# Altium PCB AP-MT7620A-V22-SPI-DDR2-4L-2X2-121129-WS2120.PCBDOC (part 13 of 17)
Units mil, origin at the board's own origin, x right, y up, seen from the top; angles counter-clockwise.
Board outline 7316 x 4279 mil, 4 copper layers (Top, Inner Layer 2, Inner Layer 3, Bottom), stack 35.4 mil thick; 640 components, 473 nets, 2041 pads, 2358 vias.
Unrouted connection lines stored in the file: 11.
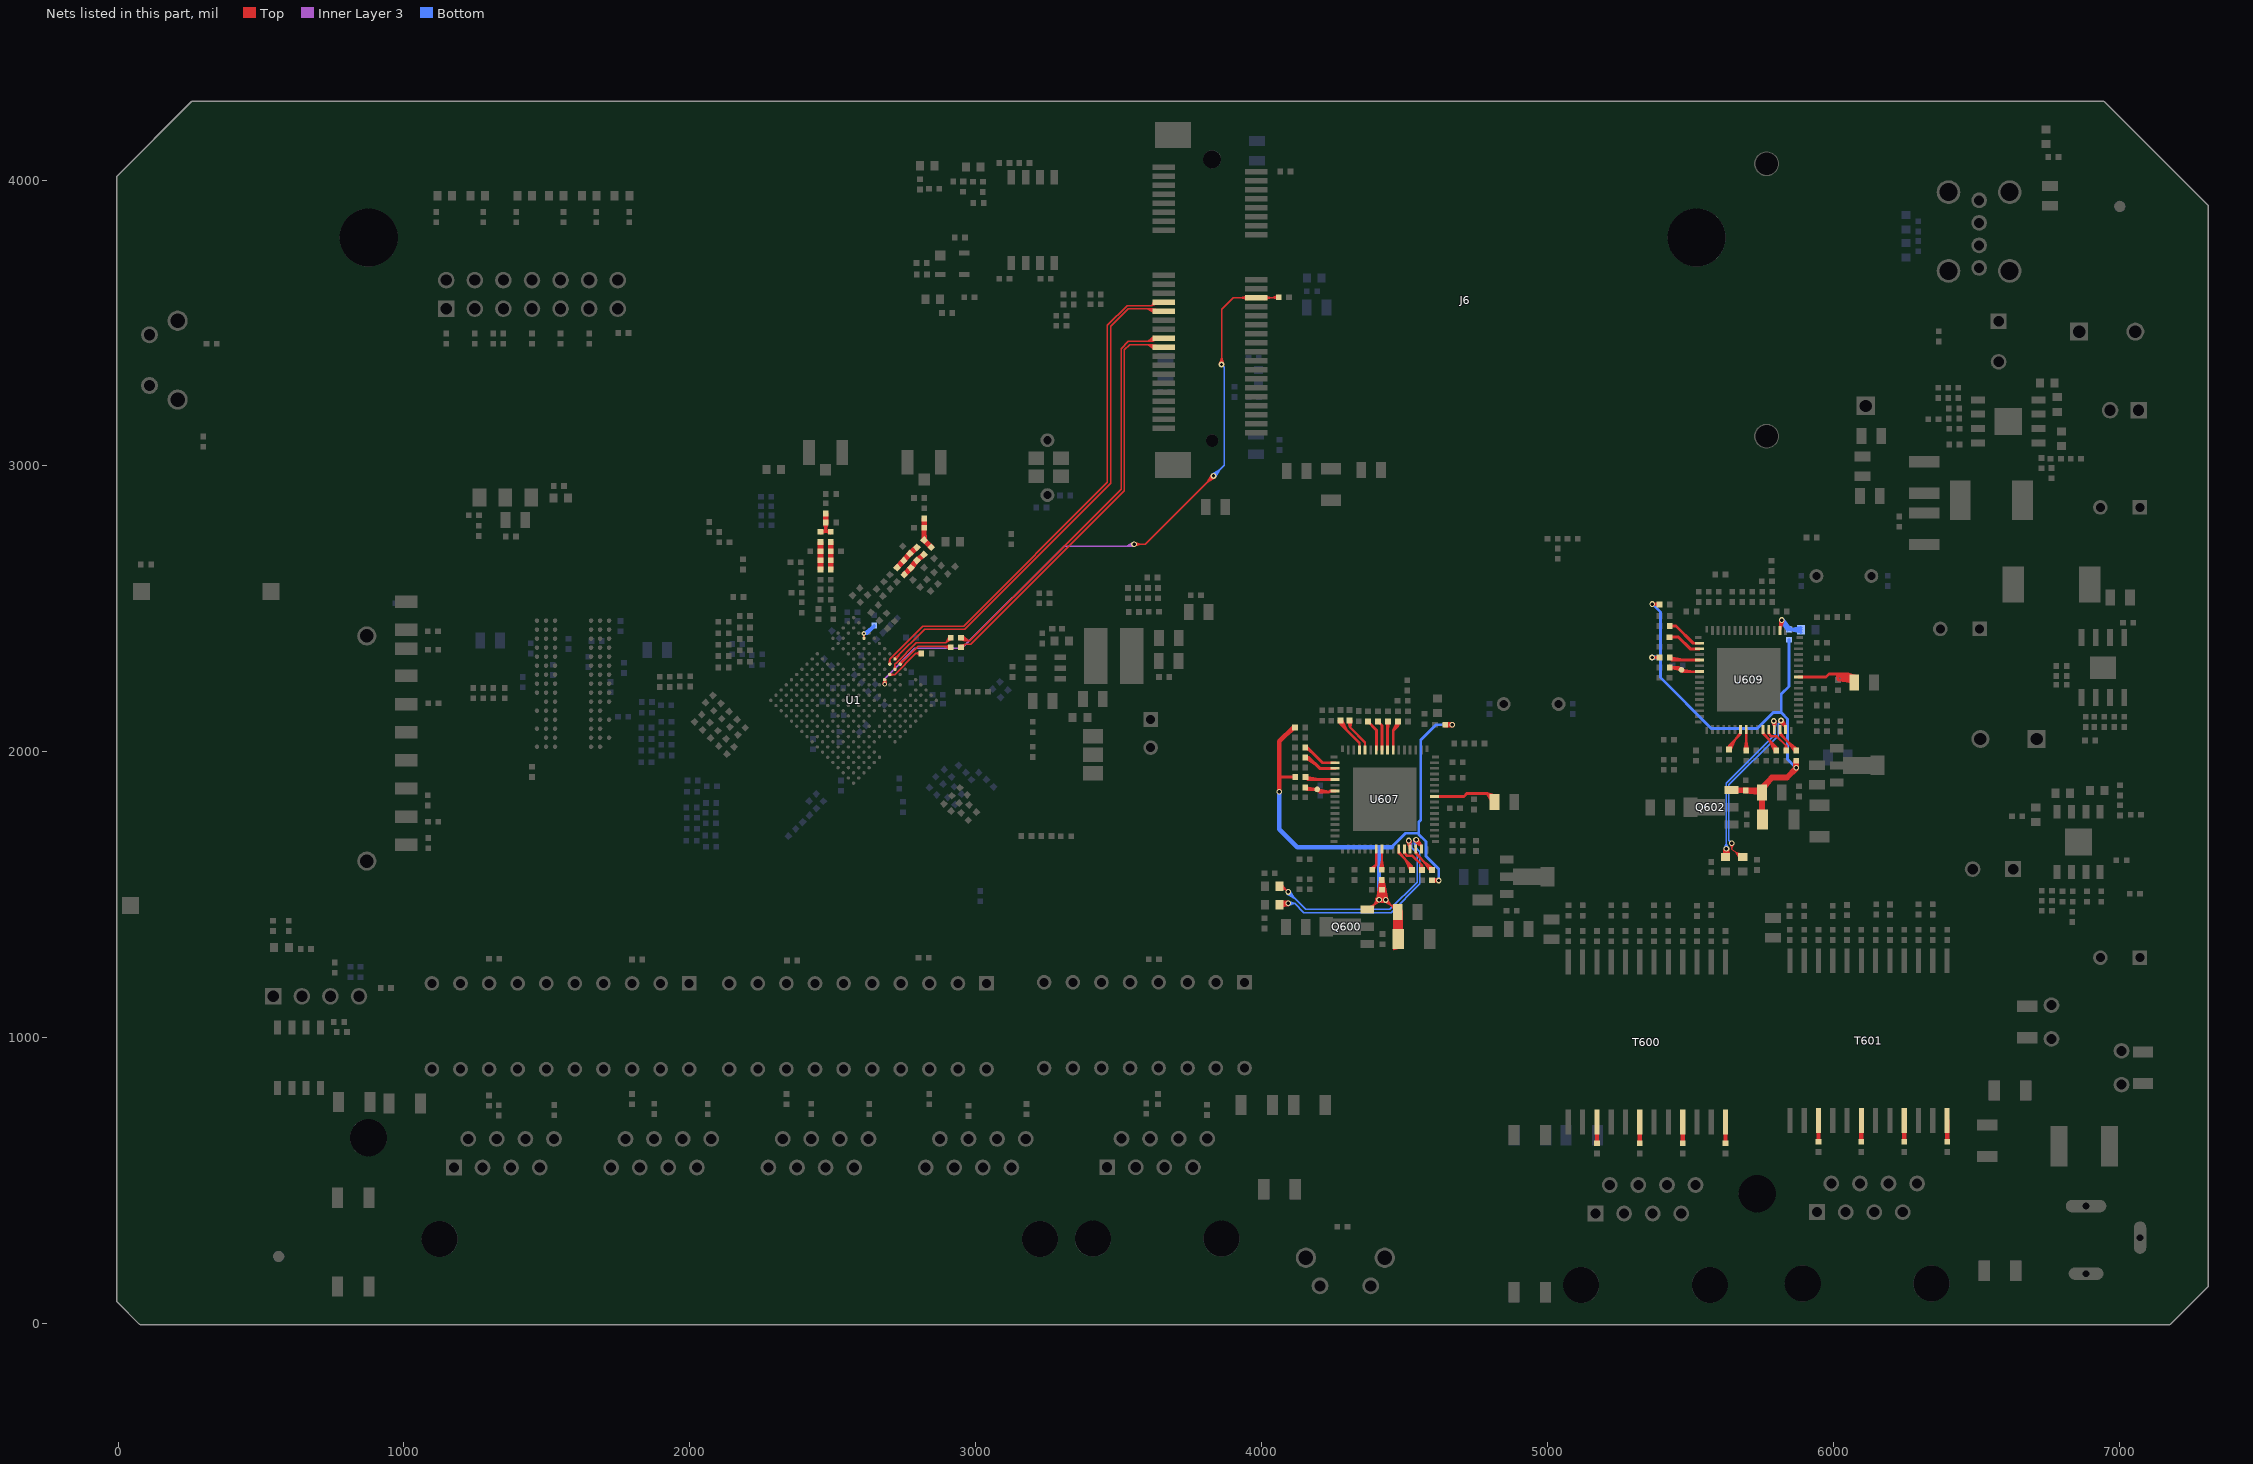
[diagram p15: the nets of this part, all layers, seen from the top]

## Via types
v1: diameter 20, hole 12, Top to Bottom, 2117 vias
v2: diameter 16, hole 8, Top to Bottom, 241 vias

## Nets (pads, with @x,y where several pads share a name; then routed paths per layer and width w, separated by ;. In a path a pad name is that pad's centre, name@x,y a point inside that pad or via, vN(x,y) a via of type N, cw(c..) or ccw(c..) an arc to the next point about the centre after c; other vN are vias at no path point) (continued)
P_LED0_IP1001: D15.1 U607.13 | length 1478.1
  Top w4.5: D15.1@4062.03,1520.92 4083,1520 ; D15.1@4062.33,1516.32 4083,1520 ; D15.1@4062.71,1525.39 4083,1520 ; D15.1@4063.59,1528 4083,1520 ; D15.1@4063.59,1530 4063.59,1520 4083,1520 ; D15.1@4064.8,1530.47 4083,1520 ; D15.1@4067.47,1534.13 4083,1520 ; D15.1@4070.93,1537.18 4083,1520 ; v1(4093,1510) 4083,1520 ; v1@4507.69,1687.78 U607.13@4517.22,1663.98 ; v1@4507.85,1687.19 U607.13@4516.91,1671.5 ; v1@4508.26,1686.17 U607.13@4519.57,1671.65 ; v1@4508.8,1685.23 U607.13@4522.19,1672.19 ; v1@4512.02,1689.08 U607.13@4517.22,1663.98 ; v1@4512.04,1688.95 U607.13@4516.91,1671.5 ; v1@4512.16,1688.5 U607.13@4519.57,1671.65 ; v1@4512.34,1688.07 U607.13@4522.19,1672.19 ; v1@4518.35,1690.48 U607.13@4522.19,1672.19 ; v1@4518.46,1690.02 U607.13@4519.57,1671.65 ; v1@4518.49,1689.54 U607.13@4516.91,1671.5 ; v1@4518.49,1689.58 U607.13@4517.22,1663.98 ; U607.13@4519.57,1660.82 4517.22,1660.82 v1@4517.22,1689.54 ; v1@4522.88,1690.86 U607.13@4522.19,1672.19 ; v1@4522.93,1688.58 U607.13@4516.91,1671.5 ; v1@4522.97,1688.96 U607.13@4517.22,1663.98 ; v1@4522.99,1689.73 U607.13@4519.57,1671.65 ; v1(4515.24,1689.54) v1@4517.22,1689.54 ; v1(4515.24,1689.54) U607.13@4517.22,1663.98 ; v1(4515.24,1689.54) U607.13@4516.91,1671.5 ; v1(4515.24,1689.54) U607.13@4522.19,1672.19 ; v1(4515.24,1689.54) U607.13@4519.57,1671.65 ; U607.13@4516.91,1671.5 v1@4517.22,1689.54 ; v1@4517.22,1689.54 U607.13@4522.19,1672.19 ; v1@4517.22,1689.54 U607.13@4519.57,1671.65
  Bottom w4.5: v1@4088.26,1503.87 4114.55,1488.45 ; v1@4090.83,1507.58 4114.55,1488.45 ; v1(4093,1510) 4154,1449 4449,1449 4544,1544 4544,1646 4525.5,1664.5 4525.5,1680.42 4516.38,1689.54 v1(4515.24,1689.54) v1@4515.7,1690 ; v1@4095.42,1512.17 4114.55,1488.45 ; v1@4099.13,1514.74 4114.55,1488.45
P_LED0_IP1001-2: D40.1 U609.13 | length 2448.2
  Top w4.5: D40.1@5613.62,1635.5 v1@5626,1660.21 ; D40.1@5617.85,1633.8 v1@5626,1660.21 ; v1@5618.25,1660.84 D40.1@5622.64,1635.62 ; v1@5618.3,1660.09 D40.1@5625.11,1635.51 ; v1@5618.35,1659.75 D40.1@5626,1637 ; v1@5618.33,1662.09 D40.1@5618.55,1636.06 ; v1@5618.43,1659.36 D40.1@5627.57,1635.53 ; v1@5618.61,1663.34 D40.1@5614.29,1636.85 ; v1@5618.78,1658.19 D40.1@5631.63,1635.82 ; v1@5619.31,1657.1 D40.1@5635.82,1636.46 ; D40.1@5622.26,1632.83 v1@5626,1660.21 ; v1@5622.76,1660.78 D40.1@5626,1637 ; v1@5622.75,1660.91 D40.1@5625.11,1635.51 ; v1@5622.76,1661.22 D40.1@5622.64,1635.62 ; v1@5622.78,1660.59 D40.1@5627.57,1635.53 ; v1@5622.83,1661.73 D40.1@5618.55,1636.06 ; v1@5622.88,1660.09 D40.1@5631.63,1635.82 ; D40.1@5623,1632.59 5627.41,1637 D40.1@5626,1637 ; v1@5622.99,1662.24 D40.1@5614.29,1636.85 ; v1@5623.06,1659.61 D40.1@5635.82,1636.46 ; D40.1@5625,1632.59 v1@5626,1660.21 ; D40.1@5627.75,1632.63 v1@5626,1660.21 ; v1@5628.83,1659.41 D40.1@5614.29,1636.85 ; v1@5629.05,1659.88 D40.1@5618.55,1636.06 ; v1@5629.09,1662.02 D40.1@5635.82,1636.46 ; v1@5629.19,1660.37 D40.1@5622.64,1635.62 ; v1@5629.21,1661.51 D40.1@5631.63,1635.82 ; v1@5629.23,1660.68 D40.1@5625.11,1635.51 ; v1@5629.24,1660.78 D40.1@5626,1637 ; v1@5629.25,1660.99 D40.1@5627.57,1635.53 ; D40.1@5632.22,1633.28 v1@5626,1660.21 ; v1@5632.41,1656.65 D40.1@5614.29,1636.85 ; v1@5633.01,1657.7 D40.1@5618.55,1636.06 ; v1@5633.44,1658.83 D40.1@5622.64,1635.62 ; v1@5633.54,1662.79 D40.1@5635.82,1636.46 ; v1@5633.61,1659.55 D40.1@5625.11,1635.51 ; v1@5633.65,1659.75 D40.1@5626,1637 ; v1@5633.72,1660.3 D40.1@5627.57,1635.53 ; v1@5633.73,1661.54 D40.1@5631.63,1635.82 ; D40.1@5636.56,1634.67 v1@5626,1660.21 ; v1@5784.34,2106.81 U609.13@5790.91,2089.84 ; v1@5784.43,2106.36 U609.13@5793.57,2082.46 ; v1@5784.59,2105.73 U609.13@5793.57,2089.65 ; v1@5784.98,2104.71 U609.13@5796.24,2089.84 ; v1@5788.75,2107.9 U609.13@5790.91,2089.84 ; v1@5788.8,2107.44 U609.13@5793.57,2089.65 ; v1@5788.78,2107.59 U609.13@5793.57,2082.46 ; v1@5788.91,2106.99 U609.13@5796.24,2089.84 ; U609.13@5793.57,2078.82 v1@5793.57,2108 ; v1@5795.21,2107.52 U609.13@5790.91,2089.84 ; v1@5795.22,2108.46 U609.13@5796.24,2089.84 ; v1@5799.46,2105.9 U609.13@5790.91,2089.84 ; v1@5799.69,2107.02 U609.13@5793.57,2089.65 ; v1@5799.72,2107.3 U609.13@5793.57,2082.46 ; v1@5799.75,2108.15 U609.13@5796.24,2089.84 ; D40.1@5614.29,1636.85 v1(5626,1661) ; D40.1@5618.55,1636.06 v1(5626,1661) ; D40.1@5622.64,1635.62 v1(5626,1661) ; D40.1@5625.11,1635.51 v1(5626,1661) ; D40.1@5626,1637 v1(5626,1661) ; v1(5626,1661) D40.1@5635.82,1636.46 ; v1(5626,1661) D40.1@5631.63,1635.82 ; v1(5626,1661) D40.1@5627.57,1635.53 ; U609.13@5790.91,2089.84 v1@5793.57,2108 ; U609.13@5790.91,2089.84 v1(5792,2108) ; v1(5792,2108) v1@5793.57,2108 ; v1(5792,2108) U609.13@5793.57,2082.46 ; v1(5792,2108) U609.13@5796.24,2089.84 ; v1(5792,2108) U609.13@5793.57,2089.65 ; U609.13@5793.57,2082.46 5795.25,2107.99 U609.13@5793.57,2089.65 ; U609.13@5793.57,2089.65 v1@5793.57,2108 ; v1@5793.57,2108 U609.13@5796.24,2089.84
  Bottom w4.5: v1@5618.42,1662.63 5626,1679.41 ; v1@5622.76,1661.29 5626,1679.41 ; v1(5626,1661) 5626,1679.41 ; v1@5629.24,1661.29 5626,1679.41 ; v1@5633.58,1662.63 5626,1679.41 ; v1@5784.67,2105.48 5797,2081.58 ; v1@5788.85,2107.2 5797,2081.58 ; v1@5795.22,2108.41 5797,2081.58 ; v1@5799.74,2108.33 5797,2081.58 ; 5626,1679.41 5625.5,1679.91 5625.5,1890.5 5797,2062 5797,2103 v1(5792,2108) 5797,2081.58
P_LED1_IP1001-2_1-CPU-RT0: R740.2 U609.14 | length 266
  Top w8: U609.14@5813.26,2078.82 5813.26,2062.05 ; 5838.34,2036.96 U609.14@5813.26,2067.99 ; R740.2@5865.41,2001.18 5843.18,2032.13 ; R740.2@5873.91,2009.59 5843.18,2032.13 ; 5813.26,2062.05 5868.99,2006.32 5868.99,2004.05 5869.99,2004.05 R740.2@5869.99,2005.05 5843.18,2032.13 ; 5813.26,2062.05 U609.14@5813.26,2067.99 ; 5813.26,2062.05 U609.14@5813.26,2067.99
P_LED1_IP1001_1-CPU-RT0: R714.2 U607.14 | length 266
  Top w8: U607.14@4539.26,1660.82 4539.26,1644.05 ; 4564.34,1618.96 U607.14@4539.26,1649.99 ; R714.2@4591.41,1583.18 4569.18,1614.13 ; R714.2@4599.91,1591.59 4569.18,1614.13 ; 4539.26,1644.05 4594.99,1588.32 4594.99,1586.05 4595.99,1586.05 R714.2@4595.99,1587.05 4569.18,1614.13 ; 4539.26,1644.05 U607.14@4539.26,1649.99 ; 4539.26,1644.05 U607.14@4539.26,1649.99
P_LED2_IP1001: D16.1 U607.15 | length 2809.2
  Top w4.5: D16.1@4063.43,1469.75 v1@4091.46,1470 ; D16.1@4063.59,1465 D16.1@4068.59,1470 ; D16.1@4063.59,1467 v1@4091.46,1470 ; D16.1@4063.75,1474.25 v1@4091.46,1470 ; D16.1@4064.02,1464.28 v1@4091.46,1470 ; D16.1@4064.81,1478.69 v1@4091.46,1470 ; D16.1@4065.29,1459.95 v1@4091.46,1470 ; D16.1@4067.27,1455.84 v1@4091.46,1470 ; v1@4088.35,1476.2 D16.1@4069.13,1456.93 ; v1@4089.33,1476.82 D16.1@4068.28,1461.1 ; v1@4089.66,1463.01 D16.1@4068.08,1477.62 ; v1@4090.38,1477.3 D16.1@4067.75,1465.06 ; v1@4090.75,1462.58 D16.1@4067.63,1473.65 ; v1@4091.06,1477.5 D16.1@4067.57,1467.43 ; v1@4091.27,1472.75 D16.1@4069.13,1456.93 ; v1@4091.71,1472.98 D16.1@4068.28,1461.1 ; v1@4091.77,1462.35 D16.1@4068.59,1470 ; v1@4091.86,1466.96 D16.1@4068.08,1477.62 ; v1@4091.89,1462.33 D16.1@4067.5,1469.78 ; v1@4092.18,1473.14 D16.1@4067.75,1465.06 ; v1@4092.33,1466.82 D16.1@4067.63,1473.65 ; v1@4092.47,1473.21 D16.1@4067.57,1467.43 ; v1@4092.6,1462.26 D16.1@4067.57,1467.43 ; v1@4092.77,1473.24 D16.1@4067.5,1469.78 ; v1@4092.78,1473.24 D16.1@4068.59,1470 ; v1@4092.93,1477.75 D16.1@4067.63,1473.65 ; v1@4093.12,1466.75 D16.1@4067.57,1467.43 ; v1@4093.26,1473.24 D16.1@4067.63,1473.65 ; v1@4093.33,1462.26 D16.1@4067.75,1465.06 ; v1@4093.42,1466.78 D16.1@4067.75,1465.06 ; v1@4093.75,1473.16 D16.1@4068.08,1477.62 ; v1@4093.91,1466.88 D16.1@4068.28,1461.1 ; v1@4094.14,1477.67 D16.1@4068.08,1477.62 ; v1@4094.39,1467.06 D16.1@4069.13,1456.93 ; v1@4094.52,1462.4 D16.1@4068.28,1461.1 ; v1@4095.72,1462.74 D16.1@4069.13,1456.93 ; v1@4534.95,1686.75 U607.15@4556.87,1669.97 ; v1@4535.5,1686.24 U607.15@4558.94,1671.65 ; v1@4535.66,1686.11 U607.15@4559.46,1672.17 ; v1@4536.1,1685.78 U607.15@4560.77,1673.59 ; v1@4537.98,1690.1 U607.15@4556.87,1669.97 ; v1@4538.2,1689.87 U607.15@4558.94,1671.65 ; v1@4538.26,1689.81 U607.15@4559.46,1672.17 ; v1@4538.43,1689.65 U607.15@4560.77,1673.59 ; v1@4542.81,1694.44 U607.15@4560.77,1673.59 ; v1@4542.97,1694.27 U607.15@4559.46,1672.17 ; v1@4543.02,1694.2 U607.15@4558.94,1671.65 ; v1@4543.21,1693.95 U607.15@4556.87,1669.97 ; v1@4546.47,1697.1 U607.15@4560.77,1673.59 ; v1@4546.8,1696.67 U607.15@4559.46,1672.17 ; v1@4546.91,1696.5 U607.15@4558.94,1671.65 ; v1@4547.3,1695.86 U607.15@4556.87,1669.97 ; U607.15@4558.94,1660.82 4559.46,1660.82 U607.15@4559.46,1672.17 ; D16.1@4067.5,1469.78 4091.76,1477.65 D16.1@4068.59,1470 ; D16.1@4067.5,1469.78 4092.82,1466.75 D16.1@4068.59,1470 ; D16.1@4067.5,1469.78 v1(4093,1470) ; D16.1@4067.57,1467.43 v1(4093,1470) ; D16.1@4067.63,1473.65 v1(4093,1470) ; D16.1@4067.75,1465.06 v1(4093,1470) ; D16.1@4068.08,1477.62 v1(4093,1470) ; D16.1@4068.28,1461.1 v1(4093,1470) ; D16.1@4068.59,1470 v1(4093,1470) ; D16.1@4068.59,1470 v1(4093,1470) ; D16.1@4069.13,1456.93 v1(4093,1470) ; v1(4540.48,1692.18) 4539.96,1691.66 U607.15@4559.46,1672.17 ; v1(4540.48,1692.18) U607.15@4556.87,1669.97 ; v1(4540.48,1692.18) U607.15@4560.77,1673.59 ; v1(4540.48,1692.18) U607.15@4558.94,1671.65 ; v1(4540.48,1692.18) U607.15@4559.46,1672.17 ; v1@4545.4,1686.23 U607.15@4556.87,1669.97 ; v1@4545.4,1686.23 U607.15@4560.77,1673.59 ; v1@4545.4,1686.23 U607.15@4558.94,1671.65
  Bottom w4.5: v1(4093,1470) 4116,1470 ; v1@4093.23,1466.76 4116,1470 ; v1@4093.23,1473.24 4116,1470 ; v1@4094.31,1462.36 4116,1470 ; v1@4094.31,1477.64 4116,1470 ; v1@4532.75,1692.71 4535,1669 ; v1@4536.18,1692.18 4535,1691 v1(4540.48,1692.18) ; v1@4537.27,1692.71 4535,1669 ; v1@4543.59,1691.22 4535,1669 ; v1@4547.63,1689.19 4535,1669 ; 4116,1470 4148,1438 4453,1438 4554,1539 4554,1650 4535,1669 ; 4535,1669 4535,1685.71 4540.97,1691.69 v1(4540.48,1692.18) ; 4535,1669 v1(4540.48,1692.18)
P_LED2_IP1001-2: D41.1 U609.15 | length 1559.4
  Top w4: v1@5637.16,1678.4 5645,1660 ; v1@5641.02,1679.6 5645,1660 ; v1(5645,1680) 5645,1660 ; v1@5648.98,1679.6 5645,1660 ; v1@5652.84,1678.4 5645,1660 ; D41.1@5671.89,1624.78 5657.22,1651.09 ; D41.1@5675.29,1626.98 5657.22,1651.09 ; D41.1@5678,1637 5676.5,1638.5 5674.5,1638.5 5645,1660 ; D41.1@5678.34,1629.6 5657.22,1651.09 ; D41.1@5681,1632.59 5657.22,1651.09 ; D41.1@5683.24,1635.9 5657.22,1651.09 ; D41.1@5685.03,1639.5 5657.22,1651.09 ; D41.1@5686.34,1643.34 5657.22,1651.09
  Top w4.5: D41.1@5678,1637 5678.59,1637 D41.1@5683,1632.59 ; v1@5811.24,2104.53 U609.15@5830.81,2088.04 ; v1@5811.81,2103.95 U609.15@5832.94,2089.65 ; v1@5812.14,2103.66 U609.15@5833.97,2090.68 ; v1@5812.44,2103.43 U609.15@5834.84,2091.53 ; v1@5814.45,2107.72 U609.15@5830.81,2088.04 ; v1@5814.66,2107.46 U609.15@5832.94,2089.65 ; v1@5814.79,2107.32 U609.15@5833.97,2090.68 ; v1@5814.9,2107.22 U609.15@5834.84,2091.53 ; v1@5819.54,2111.76 U609.15@5834.84,2091.53 ; v1@5819.63,2111.64 U609.15@5833.97,2090.68 ; v1@5819.74,2111.49 U609.15@5832.94,2089.65 ; v1@5819.92,2111.2 U609.15@5830.81,2088.04 ; v1@5823.37,2114.15 U609.15@5834.84,2091.53 ; v1@5823.58,2113.85 U609.15@5833.97,2090.68 ; v1@5823.81,2113.48 U609.15@5832.94,2089.65 ; v1@5824.17,2112.76 U609.15@5830.81,2088.04 ; U609.15@5832.94,2078.82 5833.97,2078.82 U609.15@5833.97,2090.68 ; v1(5817.07,2109.64) 5816.04,2108.61 U609.15@5833.97,2090.68 ; v1(5817.07,2109.64) U609.15@5833.97,2090.68 ; v1(5817.07,2109.64) U609.15@5830.81,2088.04 ; v1(5817.07,2109.64) U609.15@5834.84,2091.53 ; v1(5817.07,2109.64) U609.15@5832.94,2089.65 ; v1@5819.65,2105 U609.15@5830.81,2088.04 ; v1@5819.65,2105 U609.15@5834.84,2091.53 ; v1@5819.65,2105 U609.15@5832.94,2089.65
  Bottom w4.5: v1(5645,1680) 5635,1690 5635,1885 5807,2057 5807,2097 ; v1@5810.03,2112.87 5807,2097 ; v1@5814.34,2111.4 5807,2097 ; v1@5819.4,2107.36 5807,2097 ; v1@5821.8,2103.49 5807,2097 ; 5807,2097 5818.35,2108.35 v1(5817.07,2109.64) 5807,2097
P_MDC_IP1001-2_1-CPU-RT0: R735.1 U609.11 | length 326.8
  Top w8: U609.11@5754.2,2078.82 5753.99,2078.61 5753.99,2063.05 ; 5778.64,2038.4 U609.11@5754.2,2067.99 ; R735.1@5794.75,2002.13 5777.24,2039.8 ; R735.1@5799.99,2004.05 R735.1@5799.99,2005.05 ; R735.1@5804.76,2008.69 5777.24,2039.8 ; 5753.99,2063.05 5799.99,2017.05 ; 5753.99,2063.05 U609.11@5754.2,2067.99 ; 5753.99,2063.05 U609.11@5754.2,2067.99 ; 5777.24,2039.8 R735.1@5799.99,2005.05 ; R735.1@5799.99,2005.05 5799.99,2017.05 ; R735.1@5799.99,2005.05 5799.99,2017.05 ; 5799.99,2017.05 5794.18,2006.55 5799.99,2017.05 ; 5799.99,2017.05 5805.8,2006.55 5799.99,2017.05
P_MDC_IP1001_1-CPU-RT0: R707.1 U607.11 | length 326.8
  Top w8: U607.11@4480.2,1660.82 4479.99,1660.61 4479.99,1645.05 ; 4504.64,1620.4 U607.11@4480.2,1649.99 ; R707.1@4520.75,1584.13 4503.24,1621.8 ; R707.1@4525.99,1586.05 R707.1@4525.99,1587.05 ; R707.1@4530.76,1590.69 4503.24,1621.8 ; 4479.99,1645.05 4525.99,1599.05 ; 4479.99,1645.05 U607.11@4480.2,1649.99 ; 4479.99,1645.05 U607.11@4480.2,1649.99 ; 4503.24,1621.8 R707.1@4525.99,1587.05 ; R707.1@4525.99,1587.05 4525.99,1599.05 ; R707.1@4525.99,1587.05 4525.99,1599.05 ; 4525.99,1599.05 4520.18,1588.55 4525.99,1599.05 ; 4525.99,1599.05 4531.8,1588.55 4525.99,1599.05
P_MDIO_IP1001-2_1-CPU-RT0: R738.1 U609.12 | length 170.7
  Top w8: U609.12@5773.89,2078.82 5772.99,2077.92 5772.99,2077 5772.99,2063.05 ; R738.1@5829.1,2006.17 5834.99,2021.05 ; R738.1@5834.99,2004.05 R738.1@5834.99,2005.05 5834.99,2021.05 ; R738.1@5840.88,2006.17 5834.99,2021.05 ; 5772.99,2063.05 5781.99,2054.05 ; 5772.99,2063.05 U609.12@5773.89,2067.99 ; 5772.99,2063.05 U609.12@5773.89,2067.99 ; U609.12@5773.89,2067.99 5781.99,2054.05 ; 5781.99,2054.05 5801.99,2054.05 5834.99,2021.05
P_MDIO_IP1001_1-CPU-RT0: R711.1 U607.12 | length 170.7
  Top w8: U607.12@4499.89,1660.82 4498.99,1659.92 4498.99,1645.05 ; R711.1@4555.1,1588.17 4560.99,1603.05 ; R711.1@4560.99,1586.05 R711.1@4560.99,1587.05 4560.99,1603.05 ; R711.1@4566.88,1588.17 4560.99,1603.05 ; 4498.99,1645.05 4507.99,1636.05 ; 4498.99,1645.05 U607.12@4499.89,1649.99 ; 4498.99,1645.05 U607.12@4499.89,1649.99 ; U607.12@4499.89,1649.99 4507.99,1636.05 ; 4507.99,1636.05 4527.99,1636.05 4560.99,1603.05
P_RXCLK_1-CPU-RT0: R708.2 U607.39 | length 205.7
  Top w10: U607.39@4460.52,2007.28 4460.52,2075.05 ; U607.39@4460.52,2018.11 4460.52,2053.03 ; R708.2@4476.99,2107.05 R708.2@4476.99,2106.05 ; 4460.52,2075.05 4476.99,2091.52 ; 4460.52,2075.05 R708.2@4476.99,2106.05 ; 4476.99,2091.52 R708.2@4476.99,2106.05 ; 4476.99,2091.52 R708.2@4476.99,2106.05 ; 4476.99,2091.52 R708.2@4476.99,2106.05
P_RXD0_1-CPU-RT0: R703.2 U607.41 | length 139.6
  Top w10: R703.2@4406.99,2106.05 4421.15,2091.89 U607.41@4421.15,2007.28 ; U607.41@4421.15,2018.11 4421.15,2053.03
P_RXD1_1-CPU-RT0: R697.2 U607.42 | length 145.9
  Top w10: R697.2@4371.99,2106.05 4401.46,2076.58 U607.42@4401.46,2007.28 ; U607.42@4401.46,2018.11 4401.46,2053.03
P_RXD2_1-CPU-RT0: R693.2 U607.44 | length 218.3
  Top w8: R693.2@4302.12,2108.81 4310,2085 ; R693.2@4314,2109.76 4310,2085 ; U607.44@4362.09,2007.28 4362.09,2032.91 ; U607.44@4362.09,2018.11 4362.09,2032.91 ; 4310,2085 4362.09,2032.91 ; 4310,2085 4310,2111 4308,2111 R693.2@4308,2110 4310,2085
P_RXD3_1-CPU-RT0: R692.2 U607.45 | length 336.9
  Top w8: R692.2@4271.19,2106.42 4299.25,2073.75 ; R692.2@4281.26,2112.88 4299.25,2073.75 ; U607.45@4342.41,2007.28 4342.41,2030.59 ; U607.45@4342.41,2018.11 4342.41,2030.59 ; 4276,2097 R692.2@4276,2110 ; 4276,2097 4342.41,2030.59 ; 4276,2097 4281.84,2108.62 4276,2097 ; 4276,2097 4270.16,2108.62 4276,2097 ; 4276,2097 R692.2@4276,2110 ; R692.2@4276,2110 4299.25,2073.75
P_RXDV_1-CPU-RT0: R702.2 U607.40 | length 176.2
  Top w10: U607.40@4440.83,2007.28 4440.83,2105.89 4441.99,2107.05 R702.2@4441.99,2106.05 4440.83,2066 ; U607.40@4440.83,2018.11 4440.83,2053.03
P_VDDO_IP1001: C654.1 C661.1 L608.2 Q600.3 R686.1 R690.1 R696.1 R714.1 R716.2 | length 6556.5
  Top w4: Q600.3@4369.35,1447.89 4369.96,1448.5 4376.5,1448.5 v1(4411,1483) ; Q600.3@4371.94,1457.6 4396.76,1468.76 ; Q600.3@4373.88,1454.02 4396.76,1468.76 ; Q600.3@4376.3,1450.81 4396.76,1468.76 ; Q600.3@4379.29,1447.89 4396.76,1468.76 ; Q600.3@4382.68,1445.47 4396.76,1468.76 ; Q600.3@4386.27,1443.65 4396.76,1468.76 ; Q600.3@4390.13,1442.36 4396.76,1468.76 ; 4397.77,1490.23 4399.5,1488.5 4399.5,1482 v1(4434,1482) ; v1@4404.62,1487.82 4390.51,1462.51 ; v1@4407.98,1485.63 4390.51,1462.51 ; R696.1@4412.21,1550.19 4421,1529.98 ; C654.1@4413,1518.23 R696.1@4417.74,1544.07 ; C654.1@4413.03,1517.35 R696.1@4414.87,1544.07 ; C654.1@4413.07,1519.04 R696.1@4420.37,1543.96 ; C654.1@4413.13,1519.45 4421,1540 ; C654.1@4413.24,1519.93 4422.4,1540.2 ; C654.1@4413.43,1520.59 4424.59,1540.82 ; v1@4413.63,1479.98 4390.51,1462.51 ; v1@4415.82,1476.62 4390.51,1462.51 ; R696.1@4416.04,1551.46 4421,1529.98 ; C654.1@4417,1517.81 R696.1@4417.74,1544.07 ; C654.1@4417.01,1518.21 R696.1@4420.37,1543.96 ; C654.1@4417.02,1518.36 4421,1540 ; C654.1@4417.05,1517.38 R696.1@4414.87,1544.07 ; C654.1@4417.05,1518.61 4422.4,1540.2 ; C654.1@4417.12,1518.96 4424.59,1540.82 ; R696.1@4420,1552 4421,1529.98 ; R696.1@4420,1553 4421,1552 C654.1@4421,1518 ; R696.1@4424,1551.82 4421,1529.98 ; C654.1@4424.81,1519.2 R696.1@4414.87,1544.07 ; C654.1@4424.92,1518.8 R696.1@4417.74,1544.07 ; C654.1@4424.99,1517.72 4424.59,1540.82 ; C654.1@4425,1518.11 4422.4,1540.2 ; C654.1@4424.98,1518.36 4421,1540 ; C654.1@4424.98,1518.41 R696.1@4420.37,1543.96 ; R696.1@4427.92,1550.91 4421,1529.98 ; C654.1@4428.43,1520.97 R696.1@4414.87,1544.07 ; C654.1@4428.69,1520.19 R696.1@4417.74,1544.07 ; C654.1@4428.94,1518.94 4422.4,1540.2 ; C654.1@4429,1518.15 4424.59,1540.82 ; v1@4429.12,1475.66 4454.23,1461.37 ; v1@4429.7,1475.25 v1@4412.73,1490.81 ; v1@4430.3,1489.09 v1@4412.05,1475.07 ; v1@4430.94,1474.61 v1@4411.52,1486.97 ; v1@4431.34,1479.01 4454.23,1461.37 ; v1@4431.6,1489.63 v1@4411.17,1479 ; v1@4432.15,1478.45 v1@4412.73,1490.81 ; v1@4432.27,1474.19 v1(4411,1483) ; v1@4432.47,1485.7 v1@4412.05,1475.07 ; v1@4432.67,1474.11 v1@4410,1482 ; v1@4432.67,1489.89 v1@4410,1482 ; v1@4432.8,1478.18 v1@4411.52,1486.97 ; v1@4432.95,1489.93 v1(4411,1483) ; v1@4433.14,1485.91 v1@4411.17,1479 ; v1@4433.48,1478.03 v1(4411,1483) ; v1@4433.65,1474.01 v1@4411.17,1479 ; v1@4433.67,1478.01 v1@4410,1482 ; v1@4433.67,1485.99 v1@4410,1482 ; v1@4433.83,1486 v1(4411,1483) ; v1@4434.17,1478 v1@4411.17,1479 ; v1@4434.34,1489.99 v1@4411.52,1486.97 ; v1@4434.52,1485.97 v1@4411.52,1486.97 ; v1@4434.87,1478.1 v1@4412.05,1475.07 ; v1@4435.05,1474.07 v1@4412.05,1475.07 ; v1@4435.2,1485.81 v1@4412.73,1490.81 ; v1@4435.73,1489.81 v1@4412.73,1490.81 ; v1@4437.04,1484.6 4454.23,1461.37 ; v1@4440.43,1486.76 4454.23,1461.37 ; L608.2@4461.01,1334.62 4462.04,1308.5 ; L608.2@4465.19,1334.45 4462.04,1308.5 ; C661.1@4466.04,1439.34 4451.06,1464.54 ; L608.2@4469.21,1333.64 4462.04,1308.5 ; C661.1@4469.41,1441.68 4451.06,1464.54 ; C661.1@4472.38,1444.42 4451.06,1464.54 ; L608.2@4473,1332.23 4462.04,1308.5 ; C661.1@4474.93,1447.52 4451.06,1464.54 ; C661.1@4476.54,1450.05 4451.06,1464.54 ; C661.1@4477.3,1438.3 4434,1481.59 v1(4434,1482) ; L608.2@4477.87,1329.3 4462.04,1308.5 ; L608.2@4477.87,1345.05 4462.04,1329.21 4462.04,1308.5 ; C661.1@4477.89,1452.73 4451.06,1464.54 ; C661.1@4479.25,1456.51 4451.06,1464.54 ; C661.1@4480.09,1460.46 4451.06,1464.54 ; C661.1@4480.37,1464.55 4451.06,1464.54 ; L608.2@4481.99,1325.39 4462.04,1308.5 ; L608.2@4484.36,1322.11 4462.04,1308.5 ; L608.2@4486.21,1318.45 4462.04,1308.5 ; L608.2@4487.49,1314.46 4462.04,1308.5 ; 4390.51,1462.51 v1(4411,1483) ; v1@4410,1482 v1(4434,1482) ; v1(4411,1483) v1(4434,1482) ; v1(4411,1483) v1(4434,1482) ; v1@4411.17,1479 v1(4434,1482) ; v1@4411.17,1479 v1(4434,1482) ; v1@4411.52,1486.97 v1(4434,1482) ; v1@4411.52,1486.97 v1(4434,1482) ; v1@4412.05,1475.07 v1(4434,1482) ; v1@4412.05,1475.07 v1(4434,1482) ; v1@4412.73,1490.81 v1(4434,1482) ; v1@4412.73,1490.81 v1(4434,1482) ; C654.1@4413.46,1520.67 4421,1529.98 ; C654.1@4413.46,1520.67 4421,1529.98 ; C654.1@4413.46,1520.67 4421,1529.98 ; C654.1@4413.46,1520.67 4421,1529.98 ; C654.1@4413.46,1520.67 4421,1529.98 ; R696.1@4414.87,1544.07 C654.1@4421,1518 ; C654.1@4417.06,1518.67 4421,1529.98 ; C654.1@4417.06,1518.67 4421,1529.98 ; C654.1@4417.06,1518.67 4421,1529.98 ; C654.1@4417.06,1518.67 4421,1529.98 ; C654.1@4417.06,1518.67 4421,1529.98 ; R696.1@4417.74,1544.07 C654.1@4421,1518 ; R696.1@4420.37,1543.96 4428.87,1519.43 4421,1540 ; R696.1@4420.37,1543.96 C654.1@4421,1518 ; C654.1@4421,1518 4424.59,1540.82 ; C654.1@4421,1518 4421,1529.98 ; C654.1@4421,1518 4421,1529.98 ; C654.1@4421,1518 4422.4,1540.2 ; C654.1@4421,1518 4421,1529.98 ; C654.1@4421,1518 4421,1529.98 ; C654.1@4421,1518 4421,1529.98 ; 4421,1529.98 C654.1@4428.54,1520.67 ; 4421,1529.98 C654.1@4424.94,1518.67 ; 4421,1529.98 C654.1@4428.54,1520.67 ; 4421,1529.98 C654.1@4424.94,1518.67 ; 4421,1529.98 C654.1@4428.54,1520.67 ; 4421,1529.98 C654.1@4424.94,1518.67 ; 4421,1529.98 C654.1@4428.54,1520.67 ; 4421,1529.98 C654.1@4424.94,1518.67 ; 4421,1529.98 C654.1@4428.54,1520.67 ; 4421,1529.98 C654.1@4424.94,1518.67 ; v1(4434,1482) 4454.23,1461.37
  Top w10: 4062,1912.05 R686.1@4117.99,1912.05 4077.99,1912.05
  Top w15: v1(4062,1860) 4062,1912.05 4062,2037 4110,2085 R690.1@4117,2085 4071.65,2046.65 ; R714.1@4595.99,1551.05 4618.95,1551.05 v1(4620,1550) R714.1@4595.99,1551.05
  Top w20: v1(4411,1483) v1(4434,1482) ; v1(4411,1483) C654.1@4421,1518 ; v1(4411,1483) C654.1@4421,1518 ; v1(4411,1483) R696.1@4420,1553 ; v1(4411,1483) R696.1@4420,1552 ; v1(4411,1483) v1(4434,1482) ; v1@4420,1482 v1(4434,1482) ; v1@4420,1482 R696.1@4420,1553 ; v1@4420,1482 R696.1@4420,1552 ; v1@4420,1482 C654.1@4421,1518 ; v1@4420,1482 C654.1@4421,1518 ; v1@4420,1482 v1(4434,1482) ; v1@4420,1482 v1(4434,1482) ; v1@4420,1482 v1(4434,1482) ; v1@4420,1482 v1(4434,1482) ; v1@4420,1482 v1(4434,1482) ; R696.1@4420,1552 C654.1@4421,1518 ; R696.1@4420,1552 v1(4434,1482) ; R696.1@4420,1553 C654.1@4421,1518 ; R696.1@4420,1553 v1(4434,1482) ; C654.1@4421,1518 v1(4434,1482) ; C654.1@4421,1518 v1(4434,1482) ; R716.2@4643,2095 v1(4667,2095) R716.2@4643,2095
  Top w35: C661.1@4476.54,1439.05 4477.3,1438.3 C661.1@4477.87,1437.72 ; C661.1@4477.87,1437.72 L608.2@4477.87,1345.05 4476.54,1428.05 4477.87,1360.8 C661.1@4477.87,1437.72
  Bottom w10: 4455.05,1666.05 4504,1715 4549,1715 4550,1716 ; v1(4620,1550) 4620,1590 4574.99,1635.01 4574.99,1686.01 4550,1711 4550,1716 ; 4625,2095 v1(4667,2095) 4610,2095 4557,2042 4557,1761.71 4550,1754.71 4550,1716
  Bottom w15: 4062,1803 v1(4062,1860) 4062,1729 4124.95,1666.05 4411,1666.05 ; 4455.05,1666.05 4411,1666.05 ; v1(4411,1483) 4411,1505 ; v1(4411,1483) v1(4434,1482) ; v1(4411,1483) 4411,1505 ; v1(4411,1483) v1(4434,1482) ; 4411,1505 v1(4434,1482) ; 4411,1505 4411,1666.05 ; 4411,1505 v1(4434,1482)
P_VDDO_IP1001-2: C660.1 C671.1 L610.2 Q602.3 R710.1 R720.1 R740.1 R741.2 | length 3408.3
  Top w4: Q602.3@5619.37,1875.5 5624,1870.87 5624,1865.89 Q602.3@5643.35,1865.89 ; v1@5862,1944.05 R740.1@5866.16,1967.86 ; v1@5862.1,1942.73 R740.1@5862.19,1967.41 ; R740.1@5862.12,1967.59 v1@5870,1947.05 ; v1@5862.42,1946.56 R740.1@5873.82,1967.86 ; v1@5862.92,1947.72 R740.1@5877.79,1967.41 ; v1@5866.01,1943.69 R740.1@5866.16,1967.86 ; R740.1@5866.01,1968.68 v1@5870,1947.05 ; v1@5866.12,1943.05 R740.1@5862.19,1967.41 ; v1@5866.12,1944.96 R740.1@5873.82,1967.86 ; v1@5866.32,1945.57 R740.1@5877.79,1967.41 ; v1@5873.68,1945.57 R740.1@5862.19,1967.41 ; v1@5873.89,1943.05 R740.1@5877.79,1967.41 ; v1@5873.88,1944.96 R740.1@5866.16,1967.86 ; R740.1@5873.97,1968.69 v1@5870,1947.05 ; v1@5873.99,1943.7 R740.1@5873.82,1967.86 ; v1@5877.08,1947.73 R740.1@5862.19,1967.41 ; v1@5877.58,1946.56 R740.1@5866.16,1967.86 ; R740.1@5877.86,1967.6 v1@5870,1947.05 ; v1@5877.9,1942.74 R740.1@5877.79,1967.41 ; v1@5878,1944.06 R740.1@5873.82,1967.86 ; R740.1@5862.19,1967.41 v1(5870,1944) ; R740.1@5866.16,1967.86 v1(5870,1944) ; v1(5870,1944) R740.1@5869.99,1969.05 v1@5870,1947.05 ; v1(5870,1944) R740.1@5877.79,1967.41 ; v1(5870,1944) R740.1@5873.82,1967.86 ; v1(5870,1944) R740.1@5869.99,1968 ; R740.1@5869.99,1968 5862.11,1945.33 R740.1@5870,1968 ; R740.1@5869.99,1968 5877.89,1945.34 R740.1@5870,1968 ; R740.1@5869.99,1968 5866.01,1944.33 R740.1@5870,1968 ; R740.1@5869.99,1968 5873.99,1944.33 R740.1@5870,1968
  Top w12: v1(5366,2330) 5391.94,2330 R710.1@5391.99,2330.05 v1(5366,2330) ; v1(5367,2517) 5390.04,2517 R720.1@5391.99,2515.05 v1(5367,2517)
  Top w20: C671.1@5750.54,1868.05 5785,1910 ; L610.2@5751.87,1763.05 5751.87,1780.67 L610.2@5750.54,1782 ; C660.1@5693.11,1865.89 C660.1@5694,1865 ; C660.1@5693.11,1865.89 Q602.3@5643.35,1865.89 C660.1@5694,1865 ; C660.1@5693.11,1865.89 5653.29,1865.89 C660.1@5694,1865 ; C660.1@5694,1865 C660.1@5695,1866 ; C660.1@5694,1865 C671.1@5748,1866 ; C660.1@5694,1865 C671.1@5750.54,1857.05 ; C660.1@5695,1866 C671.1@5748,1866 ; C660.1@5695,1866 C671.1@5750.54,1857.05 ; C671.1@5748,1866 5750.54,1863.46 C671.1@5750.54,1857.05 ; L610.2@5750.54,1782 C671.1@5750.54,1857.05 ; L610.2@5750.54,1782 5750.54,1846.05 5751.87,1778.8 C671.1@5750.54,1857.05 ; C671.1@5750.54,1857.05 5750.54,1875.54 5785,1910 ; 5785,1910 5838,1910 ; 5838,1910 5869.99,1941.99 R740.1@5869.99,1969.05 v1(5870,1944) 5838,1910
  Bottom w8: v1(5366,2330) 5395,2330 ; v1@5366.62,2324.03 5395,2330 ; v1@5366.62,2335.97 5395,2330
  Bottom w10: v1(5367,2517) 5395,2489 5395,2330 5395,2260 5573,2082 5733.95,2082 5788.95,2137 5818,2137 ; R741.2@5845,2392 5845,2229 5818,2202 5818,2137 ; 5818,2137 5818.28,2137 5840,2115.28 5840,1974 ; 5840,1974 v1(5870,1944) 5840,1974
PA0_OUT+_1-CPU-RT0: C84.2 C85.1 C86.2 L6.1 | length 1550.2
  Top w8: C84.2@2720.71,2648.42 C86.2@2743.65,2672.56 ; C84.2@2722.34,2649.85 C86.2@2752.1,2664.11 ; C84.2@2729.37,2640.19 C86.2@2752.1,2664.11 ; C84.2@2730.71,2641.88 C86.2@2743.65,2672.56 ; C86.2@2743.42,2672.26 L6.1@2765.6,2697.58 ; C86.2@2744.99,2673.75 L6.1@2774.04,2689.14 ; C86.2@2752.41,2664.38 L6.1@2774.04,2689.14 ; C86.2@2753.67,2666.11 L6.1@2765.6,2697.58 ; C85.1@2789.21,2718.2 L6.1@2774.6,2689.66 ; C85.1@2789.57,2718.7 L6.1@2776,2696.71 ; C85.1@2789.9,2719.09 L6.1@2770.23,2693.77 ; C85.1@2790.74,2719.83 L6.1@2766.7,2698.62 ; C85.1@2796.84,2709.56 L6.1@2766.7,2698.62 ; C85.1@2797.8,2710.13 L6.1@2770.23,2693.77 ; C85.1@2797.99,2710.28 L6.1@2776,2696.71 ; C85.1@2798.65,2710.88 L6.1@2774.6,2689.66 ; C84.2@2725.42,2644.7 C84.2@2725.42,2645.87 ; C84.2@2725.42,2644.7 C86.2@2748.27,2668.73 ; C84.2@2725.42,2644.7 C86.2@2752.1,2664.11 ; C84.2@2725.42,2644.7 C86.2@2743.65,2672.56 ; C84.2@2725.42,2644.7 C86.2@2748.27,2668.73 ; C84.2@2725.42,2645.87 C86.2@2748.27,2668.73 ; C84.2@2725.42,2645.87 C86.2@2752.1,2664.11 ; C84.2@2725.42,2645.87 C86.2@2743.65,2672.56 ; C84.2@2725.42,2645.87 C86.2@2748.27,2668.73 ; C86.2@2748.27,2668.73 C86.2@2748.27,2671.81 ; C86.2@2748.27,2668.73 L6.1@2770.23,2693.77 ; C86.2@2748.27,2668.73 L6.1@2774.04,2689.14 ; C86.2@2748.27,2668.73 L6.1@2765.6,2697.58 ; C86.2@2748.27,2668.73 L6.1@2770.23,2693.77 ; C86.2@2748.27,2668.73 2721.46,2649.21 C86.2@2748.27,2668.73 ; C86.2@2748.27,2668.73 2730.12,2640.97 C86.2@2748.27,2668.73 ; C86.2@2748.27,2671.81 L6.1@2770.23,2693.77 ; C86.2@2748.27,2671.81 L6.1@2774.04,2689.14 ; C86.2@2748.27,2671.81 L6.1@2765.6,2697.58 ; C86.2@2748.27,2671.81 L6.1@2770.23,2693.77 ; L6.1@2766.7,2698.62 C85.1@2794.27,2714.98 ; L6.1@2766.7,2698.62 C85.1@2794.27,2714.98 ; L6.1@2770.23,2693.77 2773.17,2696.71 L6.1@2776,2696.71 ; L6.1@2770.23,2693.77 C85.1@2794.27,2714.98 ; L6.1@2770.23,2693.77 2744.14,2673.07 L6.1@2770.23,2693.77 ; L6.1@2770.23,2693.77 2753.12,2665.19 L6.1@2770.23,2693.77 ; L6.1@2770.23,2693.77 C85.1@2794.27,2714.98 ; L6.1@2774.6,2689.66 C85.1@2794.27,2714.98 ; L6.1@2774.6,2689.66 C85.1@2794.27,2714.98 ; L6.1@2776,2696.71 C85.1@2794.27,2714.98 ; L6.1@2776,2696.71 C85.1@2794.27,2714.98
PA0_OUT-_1-CPU-RT0: C86.1 C89.2 C90.1 L8.1 | length 1301.6
  Top w8: C86.1@2768.52,2646.25 C89.2@2754.75,2616.08 ; C86.1@2768.68,2646.52 C90.1@2789.61,2673.51 ; C86.1@2769.12,2647.11 C89.2@2750.41,2619.95 ; C86.1@2769.14,2647.14 C89.2@2750.17,2619.95 ; C86.1@2769.91,2647.9 C89.2@2746.35,2624.58 ; C86.1@2770.15,2648.09 C90.1@2798.05,2665.07 ; C86.1@2776.65,2638.03 C89.2@2746.35,2624.58 ; C86.1@2778.13,2639.19 C90.1@2798.05,2665.07 ; C86.1@2778.32,2639.41 C89.2@2754.75,2616.08 ; C86.1@2779.26,2640.96 C90.1@2789.61,2673.51 ; C90.1@2790.03,2673.97 L8.1@2814.78,2694.48 ; C90.1@2790.49,2674.39 L8.1@2814.78,2690.23 ; C90.1@2790.89,2674.69 L8.1@2819.02,2690.23 ; C90.1@2791.87,2675.23 L8.1@2822.4,2685.28 ; C90.1@2797.65,2664.77 L8.1@2822.4,2685.28 ; C90.1@2798.51,2665.49 L8.1@2819.02,2690.23 ; C90.1@2798.93,2665.95 L8.1@2814.78,2690.23 ; C90.1@2799.23,2666.35 L8.1@2814.78,2694.48 ; C89.2@2746.35,2624.58 C86.1@2773.73,2643.27 ; C89.2@2750.17,2619.95 C89.2@2750.41,2619.95 ; C89.2@2750.17,2619.95 C86.1@2773.73,2643.27 ; C89.2@2750.17,2619.95 2777.55,2638.64 C89.2@2750.41,2619.95 ; C89.2@2750.41,2619.95 C86.1@2773.73,2643.27 ; C89.2@2754.75,2616.08 C86.1@2773.73,2643.27 ; C86.1@2773.73,2643.27 C86.1@2773.73,2649.18 ; C86.1@2773.73,2643.27 C90.1@2794.27,2669.73 ; C86.1@2773.73,2643.27 C90.1@2798.05,2665.07 ; C86.1@2773.73,2643.27 C90.1@2789.61,2673.51 ; C86.1@2773.73,2643.27 C90.1@2794.27,2669.73 ; C86.1@2773.73,2649.18 C90.1@2794.27,2669.73 ; C86.1@2773.73,2649.18 C90.1@2798.05,2665.07 ; C86.1@2773.73,2649.18 C90.1@2789.61,2673.51 ; C86.1@2773.73,2649.18 C90.1@2794.27,2669.73 ; C90.1@2794.27,2669.73 L8.1@2814.78,2690.23 ; C90.1@2794.27,2669.73 L8.1@2822.4,2685.28 ; C90.1@2794.27,2669.73 L8.1@2814.78,2694.48 ; C90.1@2794.27,2669.73 L8.1@2819.02,2690.23 ; C90.1@2794.27,2669.73 2769.34,2647.36 C90.1@2794.27,2669.73 ; C90.1@2794.27,2669.73 2778.78,2640.03 C90.1@2794.27,2669.73 ; L8.1@2814.78,2690.23 L8.1@2819.02,2690.23
PA0_OUT_1_1-CPU-RT0: C85.2 C87.1 L7.1 L8.2 | length 1518.9
  Top w8: C85.2@2813.73,2740.18 C87.1@2815.13,2776.97 ; C85.2@2813.75,2740.91 2819.73,2778.58 2825.71,2740.91 C87.1@2819.96,2778.49 ; C85.2@2813.75,2740.95 C87.1@2819.96,2778.49 ; C85.2@2813.87,2741.74 C87.1@2824.74,2776.85 ; C87.1@2814.02,2783.52 C85.2@2819.73,2750 ; C87.1@2814.03,2783.44 L7.1@2814.03,2815.44 ; C87.1@2814.24,2785.67 L7.1@2825.97,2815.44 ; C85.2@2815.15,2736.57 L8.2@2839.4,2712.52 ; C85.2@2816.72,2735.25 L8.2@2847.64,2720.77 ; C85.2@2823.6,2745.02 L8.2@2847.64,2720.77 ; C85.2@2824.92,2743.45 L8.2@2839.4,2712.52 ; C85.2@2825.6,2741.67 C87.1@2815.13,2776.97 ; C85.2@2825.72,2740.11 C87.1@2824.74,2776.85 ; C87.1@2825.76,2785.67 L7.1@2814.03,2815.44 ; C87.1@2825.97,2783.42 C85.2@2819.73,2750 ; C87.1@2825.97,2783.44 L7.1@2825.97,2815.44 ; L8.2@2839.88,2711.84 C85.2@2820.44,2739.74 ; L8.2@2848.33,2720.29 C85.2@2820.44,2739.74 ; L7.1@2814.03,2815.44 C87.1@2820,2784 ; L7.1@2814.03,2815.44 C87.1@2820,2784 ; C87.1@2815.13,2776.97 C85.2@2819.73,2740.44 ; C85.2@2819.73,2740.44 L8.2@2844.48,2715.69 C85.2@2820.44,2739.74 ; C85.2@2819.73,2740.44 2819.73,2784 C87.1@2820,2784 ; C85.2@2819.73,2740.44 L8.2@2843.77,2716.4 ; C85.2@2819.73,2740.44 L8.2@2839.4,2712.52 ; C85.2@2819.73,2740.44 L8.2@2847.64,2720.77 ; C85.2@2819.73,2740.44 L8.2@2843.77,2716.4 ; C85.2@2819.73,2740.44 C87.1@2824.74,2776.85 ; C85.2@2819.73,2740.44 C87.1@2819.96,2778.49 ; C85.2@2819.73,2750 C87.1@2820,2784 ; C87.1@2820,2784 L7.1@2820,2816 ; C87.1@2820,2784 L7.1@2825.97,2815.44 ; C87.1@2820,2784 L7.1@2820,2816 ; L7.1@2820,2816 2814.03,2784.56 L7.1@2820,2816 ; L7.1@2820,2816 2825.97,2784.56 L7.1@2820,2816 ; L8.2@2843.77,2716.4 2824.33,2744.29 L8.2@2843.77,2716.4 ; L8.2@2843.77,2716.4 2815.88,2735.84 L8.2@2843.77,2716.4
PA1_OUT+_1-CPU-RT0: C95.2 C96.1 C101.2 L9.1 | length 1120
  Top w8: C96.1@2487.03,2733.44 L9.1@2493,2702 ; C96.1@2487.03,2734.56 L9.1@2487.03,2702.56 ; C101.2@2487.24,2668.33 C95.2@2498.97,2638.56 ; C101.2@2487.24,2671.67 L9.1@2498.97,2701.44 ; C96.1@2487.24,2732.33 L9.1@2498.97,2702.56 ; C101.2@2498.76,2668.33 C95.2@2487.03,2638.56 ; C101.2@2498.76,2671.67 L9.1@2487.03,2701.44 ; C96.1@2498.76,2732.33 L9.1@2487.03,2702.56 ; C96.1@2498.97,2733.44 L9.1@2493,2702 ; C96.1@2498.97,2734.56 L9.1@2498.97,2702.56 ; C95.2@2487.03,2638.56 C101.2@2493,2670 ; C95.2@2487.03,2638.56 C101.2@2487.03,2670.56 ; C95.2@2487.03,2638.56 C101.2@2493,2670 ; C101.2@2487.03,2670.56 L9.1@2493,2702 ; C101.2@2487.03,2670.56 L9.1@2493,2702 ; L9.1@2487.03,2701.44 C101.2@2493,2670 ; L9.1@2487.03,2701.44 2487.03,2669.44 C95.2@2493,2638 ; L9.1@2487.03,2701.44 C101.2@2493,2670 ; L9.1@2487.03,2702.56 C96.1@2493,2734 ; L9.1@2487.03,2702.56 C96.1@2493,2734 ; C95.2@2493,2638 C101.2@2493,2670 ; C95.2@2493,2638 2498.97,2669.44 L9.1@2498.97,2701.44 ; C95.2@2493,2638 C101.2@2493,2670 ; C101.2@2493,2670 L9.1@2493,2702 ; C101.2@2493,2670 L9.1@2498.97,2701.44 ; C101.2@2493,2670 L9.1@2493,2702 ; C101.2@2493,2670 C95.2@2498.97,2638.56 ; L9.1@2493,2702 C96.1@2493,2734 ; L9.1@2493,2702 C96.1@2493,2734 ; L9.1@2493,2702 C101.2@2498.97,2670.56 ; L9.1@2493,2702 C101.2@2498.97,2670.56 ; C96.1@2493,2734 L9.1@2498.97,2702.56 ; C95.2@2498.97,2638.56 C101.2@2498.97,2670.56
PA1_OUT-_1-CPU-RT0: C101.1 C102.2 C105.1 L11.1 | length 1184
  Top w8: C101.1@2451.24,2668.33 C102.2@2462.97,2638.56 ; C101.1@2451.24,2671.67 C105.1@2462.97,2701.44 ; C105.1@2451.24,2703.67 L11.1@2462.97,2733.44 ; C101.1@2462.76,2668.33 C102.2@2451.03,2638.56 ; C101.1@2462.76,2671.67 C105.1@2451.03,2701.44 ; C105.1@2462.76,2703.67 L11.1@2451.03,2733.44 ; C102.2@2451.03,2638.56 C101.1@2457,2670 ; C102.2@2451.03,2638.56 C101.1@2451.03,2670.56 ; C102.2@2451.03,2638.56 C101.1@2457,2670 ; C101.1@2451.03,2670.56 C105.1@2457,2702 ; C101.1@2451.03,2670.56 C105.1@2457,2702 ; C105.1@2451.03,2701.44 C101.1@2457,2670 ; C105.1@2451.03,2701.44 L11.1@2451.03,2733.44 ; C105.1@2451.03,2701.44 2451.03,2669.44 C102.2@2457,2638 ; C105.1@2451.03,2701.44 C101.1@2457,2670 ; L11.1@2451.03,2733.44 C105.1@2457,2702 ; L11.1@2451.03,2733.44 C105.1@2457,2702 ; C102.2@2457,2638 C101.1@2457,2670 ; C102.2@2457,2638 2462.97,2669.44 C105.1@2462.97,2701.44 ; C102.2@2457,2638 C101.1@2457,2670 ; C101.1@2457,2670 C105.1@2457,2702 ; C101.1@2457,2670 C105.1@2462.97,2701.44 ; C101.1@2457,2670 C105.1@2457,2702 ; C101.1@2457,2670 C102.2@2462.97,2638.56 ; C105.1@2457,2702 L11.1@2457,2734 ; C105.1@2457,2702 L11.1@2462.97,2733.44 ; C105.1@2457,2702 L11.1@2457,2734 ; C105.1@2457,2702 C101.1@2462.97,2670.56 ; C105.1@2457,2702 C101.1@2462.97,2670.56 ; L11.1@2457,2734 2451.03,2702.56 L11.1@2457,2734 ; L11.1@2457,2734 2462.97,2702.56 L11.1@2457,2734 ; C102.2@2462.97,2638.56 C101.1@2462.97,2670.56 ; C105.1@2462.97,2701.44 L11.1@2462.97,2733.44
PA1_OUT_1_1-CPU-RT0: C96.2 C99.1 L10.1 L11.2 | length 669
  Top w8: L11.2@2457,2770 2476,2770 ; L11.2@2457.95,2764.08 2476,2770 ; L11.2@2457.95,2775.92 2476,2770 ; C99.1@2470.24,2803.67 L10.1@2481.97,2833.44 ; C99.1@2481.76,2803.67 L10.1@2470.03,2833.44 ; C96.2@2491.94,2764.09 2476,2770 ; C96.2@2491.94,2775.91 2476,2770 ; L10.1@2470.03,2833.44 C99.1@2476,2802 ; L10.1@2470.03,2833.44 2470.03,2801.44 2476,2770 ; L10.1@2470.03,2833.44 C99.1@2476,2802 ; 2476,2770 C99.1@2476,2802 ; 2476,2770 C96.2@2493,2770 2476,2770 ; 2476,2770 2481.97,2801.44 L10.1@2481.97,2833.44 ; 2476,2770 C99.1@2476,2802 ; C99.1@2476,2802 L10.1@2476,2834 ; C99.1@2476,2802 L10.1@2481.97,2833.44 ; C99.1@2476,2802 L10.1@2476,2834 ; L10.1@2476,2834 2470.03,2802.56 L10.1@2476,2834 ; L10.1@2476,2834 2481.97,2802.56 L10.1@2476,2834
PADDR0_IP1001-2_1-CPU-RT0: R728.1 U609.8 | length 206.8
  Top w8: R728.1@5689.02,2005.61 5695.15,2039.05 ; U609.8@5695.15,2067.99 5695.15,2039.07 ; U609.8@5695.15,2078.82 5695.15,2004.21 5694.99,2004.05 R728.1@5694.99,2005.05 5695.15,2039.05 ; R728.1@5700.97,2005.55 5695.15,2039.05
PADDR0_IP1001_1-CPU-RT0: R696.2 U607.8 | length 207.1
  Top w8: R696.2@4414.04,1588.73 4421.15,1622.04 ; 4421.15,1621.07 U607.8@4421.15,1649.99 ; U607.8@4421.15,1660.82 4421.15,1587 4420,1587 R696.2@4420,1588 4421.15,1622.04 ; R696.2@4425.99,1588.33 4421.15,1622.04
PADDR1_IP1001-2_1-CPU-RT0: R721.1 U609.7 | length 314.8
  Top w8: R721.1@5630.14,2011.52 5655.72,2041.72 ; R721.1@5640.34,2005.26 5655.72,2041.72 ; 5657.48,2043.48 U609.7@5675.46,2067.99 ; U609.7@5675.46,2078.82 5675.46,2061.46 ; R721.1@5635,2008 5635,2021 ; R721.1@5635,2008 5655.72,2041.72 ; R721.1@5635,2008 5635,2021 ; 5635,2021 5675.46,2061.46 ; 5635,2021 5629.16,2009.38 5635,2021 ; 5635,2021 5640.84,2009.38 5635,2021 ; 5675.46,2061.46 U609.7@5675.46,2067.99 ; 5675.46,2061.46 U609.7@5675.46,2067.99
PADDR1_IP1001_1-CPU-RT0: R691.1 U607.7 | length 177
  Top w8: R691.1@4382.85,1592.33 4401.46,1606 ; R691.1@4392.13,1584.88 4401.46,1606 ; 4401.46,1621.07 U607.7@4401.46,1649.99 ; U607.7@4401.46,1660.82 4401.46,1606 ; 4401.46,1606 4387,1591.54 R691.1@4387,1588 4401.46,1606
PADDR2_IP1001-2_1-CPU-RT0: R710.2 U609.53 | length 190.3
  Top w10: 5473.75,2320.95 R710.2@5427.99,2330.05 5434.99,2323.05 5434.99,2320.95 U609.53@5531.76,2320.95 ; 5486.01,2320.95 U609.53@5520.93,2320.95
PADDR2_IP1001_1-CPU-RT0: R686.2 U607.53 | length 191.8
  Top w10: 4199.75,1902.95 R686.2@4153.99,1912.05 4152.99,1912.05 4152.99,1910.95 4160.99,1902.95 U607.53@4257.76,1902.95 ; 4212.01,1902.95 U607.53@4246.93,1902.95
PADDR3_IP1001-2_1-CPU-RT0: R694.1 U609.51 | length 176.7
  Top w10: U609.51@5520.93,2360.32 5499.68,2360.32 ; U609.51@5531.76,2360.32 5499.68,2360.32 ; 5457.72,2402.28 5427.28,2402.28 5426,2401 R694.1@5427,2401 5457.72,2402.28 ; 5457.72,2402.28 5499.68,2360.32
PADDR3_IP1001_1-CPU-RT0: R678.1 U607.51 | length 212.4
  Top w10: 4190.13,1955.55 R678.1@4153,1980 ; 4212.01,1942.32 U607.51@4246.93,1942.32 ; U607.51@4257.76,1942.32 4203.37,1942.32 4165.68,1980 ; R678.1@4153,1980 4165.68,1980 ; R678.1@4153,1980 4165.68,1980
PADDR4_IP1001-2_1-CPU-RT0: R698.1 U609.50 | length 139.5
  Top w10: R698.1@5428,2440 5450,2440 5510,2380 ; U609.50@5520.93,2380 5510,2380 ; U609.50@5531.76,2380 5510,2380
PADDR4_IP1001_1-CPU-RT0: R679.1 U607.50 | length 205.2
  Top w10: 4187.82,1987.2 R679.1@4153,2015 4160.02,2015 4213.02,1962 ; U607.50@4246.93,1962 4213.02,1962 ; U607.50@4257.76,1962 4213.02,1962
PCAP_IP1001-2_1-CPU-RT0: C686.1 U609.25 | length 858.3
  Top w10: U609.25@5878.22,2261.89 5974.42,2261.89 5984.58,2272.05 6053,2272.05 ; U609.25@5889.05,2261.89 5923.97,2261.89 ; C686.1@6073.54,2242.05 6071,2242.05 6071,2254.05 6053,2272.05 ; C686.1@6076.07,2264.78 6013.91,2272.05 ; 6013.91,2272.05 6068.82,2242.02 6039,2250 ; 6013.91,2272.05 C686.1@6073.54,2253.05 ; 6013.91,2272.05 6016,2251 ; 6013.91,2272.05 6039,2250 ; 6013.91,2272.05 6039,2250 ; 6016,2251 6063.21,2245.09 6039,2250 ; 6016,2251 6039,2250 ; 6039,2250 C686.1@6073.54,2253.05 ; 6053,2272.05 6063.69,2246.19 6053,2272.05 ; 6053,2272.05 6079.61,2263.4 6053,2272.05 ; 6053,2272.05 C686.1@6073.54,2253.05 ; 6053,2272.05 C686.1@6073.54,2253.05
PCAP_IP1001_1-CPU-RT0: C680.1 U607.25 | length 358.2
  Top w10: U607.25@4604.22,1843.89 4707.99,1843.89 4717.99,1854.05 4790,1854.05 ; U607.25@4615.05,1843.89 4649.97,1843.89 ; C680.1@4805.5,1827.16 4790,1854.05 ; C680.1@4814.54,1824.05 4814.54,1829.51 4790,1854.05 ; C680.1@4814.54,1835.05 4790,1854.05 ; C680.1@4819.91,1845.78 4790,1854.05
PCIE_REXT_1-CPU-RT0: R381.1 U1.C10 | length 289
  Top w4.5: U1.C10@2700.04,2266.84 2717.56,2270.48 ; U1.C10@2700.04,2274.11 2717.56,2270.48 ; R381.1@2808.41,2336.41 2791.09,2344 ; R381.1@2808.41,2351.59 2791.09,2344 ; R381.1@2809.72,2340.76 2791.09,2344 ; R381.1@2809.72,2347.24 2791.09,2344 ; 2717.56,2270.48 U1.C10@2699.67,2270.48 2717.56,2270.48 ; 2717.56,2270.48 2791.09,2344 ; 2791.09,2344 R381.1@2810,2344 2791.09,2344
PCIE_RST#: C217.1 J6.22 U1.D10 | length 3456.2
  Top w4.5: v2@2675.96,2236.08 U1.D10@2677.94,2251.93 ; v2@2676.41,2238.65 U1.D10@2685.21,2251.99 ; v2@2686.95,2238.73 U1.D10@2677.94,2251.93 ; v2@2687.45,2236.17 U1.D10@2685.21,2251.99 ; v1(3554,2726) 3593,2726 v1(3832,2965) ; v1@3554.21,2722.76 3579.5,2726 ; v1@3554.21,2729.24 3579.5,2726 ; v1@3555.18,2718.34 3579.5,2726 ; v1@3555.18,2733.66 3579.5,2726 ; v1@3825.87,2969.74 3810.45,2943.45 ; v1@3829.58,2967.17 3810.45,2943.45 ; v1@3834.17,2962.58 3810.45,2943.45 ; v1@3836.74,2958.87 3810.45,2943.45 ; v1@3852.34,3356.18 3860,3380.5 ; v1@3856.76,3355.21 3860,3380.5 ; v1(3860,3355) 3860,3547.31 3901,3588.31 J6.22@3980.83,3588.31 4058.31,3588.31 C217.1@4060,3590 4036.37,3588.31 ; v1@3863.24,3355.21 3860,3380.5 ; v1@3867.66,3356.18 3860,3380.5 ; J6.22@3950.07,3580.82 3927.96,3588.31 ; J6.22@3950.07,3595.8 3927.96,3588.31 ; J6.22@3951.1,3585.22 3927.96,3588.31 ; J6.22@3951.1,3591.39 3927.96,3588.31 ; J6.22@3951.31,3588.31 3927.96,3588.31 ; J6.22@4010.36,3588.31 4033.7,3588.31 ; J6.22@4010.57,3585.22 4033.7,3588.31 ; J6.22@4010.57,3591.39 4033.7,3588.31 ; J6.22@4011.6,3580.82 4033.7,3588.31 ; J6.22@4011.6,3595.8 4033.7,3588.31 ; C217.1@4058.19,3597.54 4036.37,3588.31 ; C217.1@4059.28,3582.28 4036.37,3588.31 ; C217.1@4059.55,3593.22 4036.37,3588.31 ; C217.1@4060.01,3586.75 4036.37,3588.31 ; U1.D10@2677.94,2251.93 v2(2681.7,2236.4) ; U1.D10@2681.57,2252.38 v2(2681.7,2236.4) ; U1.D10@2681.57,2252.38 v2(2681.7,2236.4) ; U1.D10@2681.57,2252.38 2676.04,2237.39 U1.D10@2681.57,2252.38 ; U1.D10@2681.57,2252.38 2687.35,2237.48 U1.D10@2681.57,2252.38 ; v2(2681.7,2236.4) U1.D10@2685.21,2251.99
  Inner Layer 3 w4.5: 2952.07,2362 3310.07,2720 3548,2720 v1(3554,2726) 3526.22,2720 ; v1@3551.35,2733.28 3526.22,2720 ; v1@3553.13,2729.13 3526.22,2720 ; v1@3554.5,2722.79 3526.22,2720 ; v1@3554.59,2718.27 3526.22,2720
  Inner Layer 3 w5: v2@2676.25,2237.16 2681.7,2256.32 ; v2(2681.7,2236.4) 2681.7,2256.32 ; v2@2687.15,2237.16 2681.7,2256.32 ; 2952.07,2362 2787.38,2362 2681.7,2256.32
  Bottom w4.5: v1@3827.26,2971.13 3853.55,2986.55 ; v1@3829.83,2967.42 3853.55,2986.55 ; v1(3832,2965) 3869,3002 3869,3346 v1(3860,3355) ; v1@3834.42,2962.83 3853.55,2986.55 ; v1@3838.13,2960.26 3853.55,2986.55
PCIE_RXN: J6.23 U1.B9 | length 1901.8
  Top w5: U1.B9@2696.28,2306.99 2699.67,2324.67 ; U1.B9@2699.67,2306.67 2699.67,2324.67 ; U1.B9@2703.06,2306.99 2699.67,2324.67 ; J6.23@3622.44,3576.74 3616,3561 ; J6.23@3628.47,3572.56 3616,3561 ; J6.23@3632.18,3566.22 3616,3561 ; J6.23@3658,3572.56 3628.56,3572.56 3628.28,3572.28 3627.28,3572.28 3616,3561 ; 2699.67,2324.67 2815,2440 2957.5,2440 3461,2943.5 3461,3492.5 3529.5,3561 3616,3561
PCIE_RXP: J6.25 U1.A9 | length 1911.3
  Top w5: U1.A9@2715.56,2327.36 2732.54,2339.54 U1.A9@2720.36,2322.56 ; U1.A9@2718,2325 U1.A9@2717.76,2324.76 2822,2429 2962,2429 2962.06,2429 3472,2938.94 3472,2939 3472,3487.94 3534.06,3550 3619,3550 3627,3542 3627,3541.06 J6.25@3658,3541.06 ; J6.25@3625.61,3534.3 3597.89,3550 ; J6.25@3628.47,3541.06 3597.89,3550 ; J6.25@3629.71,3548.3 3597.89,3550
PCIE_TX_N: C81.2 J6.33 | length 1663.3
  Top w5: C81.2@2945.62,2372.69 2962.46,2377 ; C81.2@2954.89,2361.35 2962.46,2377 ; J6.33@3625,3408.61 3603.13,3424.5 ; J6.33@3630.07,3422.24 3603.13,3424.5 ; J6.33@3658,3415.08 3626.5,3415.08 3617.08,3424.5 ; 2962.46,2377 2950.23,2364.77 2949,2364.77 C81.2@2949,2366 2962.46,2377 ; 2962.46,2377 2981.5,2377 2983.06,2377 3520,2913.94 3520,2915.5 3520,3405.94 3538.56,3424.5 3617.08,3424.5 ; 3603.13,3424.5 J6.33@3628.47,3415.08 ; 3617.08,3424.5 3622.53,3410.76 3617.08,3424.5 ; 3617.08,3424.5 3631.6,3421.72 3617.08,3424.5 ; 3617.08,3424.5 J6.33@3628.47,3415.08 ; 3617.08,3424.5 J6.33@3628.47,3415.08
PCIE_TX_P: C80.2 J6.31 | length 1775.9
  Top w5: C80.2@2947.11,2391.74 2976.36,2388 ; C80.2@2952.66,2405.55 2976.36,2388 ; J6.31@3624.69,3452.87 3602.91,3435.5 ; J6.31@3630.48,3439.51 3602.91,3435.5 ; J6.31@3658,3446.57 3630.5,3446.57 3619.43,3435.5 ; C80.2@2949,2399 2960,2388 ; C80.2@2949,2399 2976.36,2388 ; C80.2@2949,2399 2960,2388 ; 2960,2388 2978.5,2388 3509,2918.5 3509,3410.5 3534,3435.5 3619.43,3435.5 ; 2960,2388 2955.43,2402.87 2960,2388 ; 2960,2388 2945.13,2392.57 2960,2388 ; 3602.91,3435.5 J6.31@3628.47,3446.57 ; 3619.43,3435.5 3632.78,3440.63 3619.43,3435.5 ; 3619.43,3435.5 3621.78,3449.6 3619.43,3435.5 ; 3619.43,3435.5 J6.31@3628.47,3446.57 ; 3619.43,3435.5 J6.31@3628.47,3446.57
PCIE_TXN_1-CPU-RT0: C81.1 U1.A10 | length 348
  Top w5: U1.A10@2733.65,2309.26 2750.64,2321.45 ; U1.A10@2738.45,2304.46 2750.64,2321.45 ; C81.1@2910.79,2358.83 2887.36,2370 ; C81.1@2913.07,2373.5 2887.36,2370 ; 2750.64,2321.45 U1.A10@2735.86,2306.67 2799.19,2370 2913,2370 C81.1@2913,2366 2887.36,2370
PCIE_TXP_1-CPU-RT0: C80.1 U1.B10 | length 356.5
  Top w5: U1.B10@2714.37,2288.89 2717.76,2306.6 ; U1.B10@2721.15,2288.89 2717.76,2306.6 ; 2721.31,2310.15 2717.76,2306.6 ; 2721.35,2310.15 2792.2,2381 2895,2381 ; C80.1@2906.97,2403.46 2895,2381 ; C80.1@2913,2399 2895,2381 ; C80.1@2917.46,2392.97 2895,2381 ; 2717.76,2306.6 U1.B10@2717.76,2288.57 2717.76,2306.6
PHYRST_N_IP1001-2_1-CPU-RT0: R741.1 RC3.1 U609.35 | length 993.7
  Top w8: v1@5814.03,2461.62 U609.35@5813.26,2425.28 ; v1@5814.07,2461.88 U609.35@5813.26,2436.11 ; v1@5825.57,2458.77 U609.35@5813.26,2436.11 ; v1@5825.78,2459.4 U609.35@5813.26,2425.28 ; U609.35@5813.26,2425.28 v1@5813.26,2454.26 ; U609.35@5813.26,2425.28 v1(5820,2461) ; U609.35@5813.26,2436.11 v1@5813.26,2454.26 ; U609.35@5813.26,2436.11 v1(5820,2461) ; v1@5813.26,2454.26 v1(5820,2461)
  Bottom w8: v1@5815,2457.69 R741.1@5838.28,2427.99 ; v1@5815.51,2457.02 R741.1@5843.61,2429.88 ; v1@5824.51,2464.96 R741.1@5849.1,2432.35 ; v1@5824.57,2464.88 R741.1@5846,2435 ; v1@5825.04,2464.25 R741.1@5843.61,2429.88 ; v1@5825.46,2463.48 R741.1@5838.28,2427.99 ; R741.1@5839.9,2424.84 v1@5822.61,2458.39 ; R741.1@5849.53,2431.93 v1@5822.61,2458.39 ; v1(5820,2461) R741.1@5846,2435 ; v1(5820,2461) R741.1@5849.1,2432.35 ; v1(5820,2461) R741.1@5838.28,2427.99 ; v1(5820,2461) R741.1@5843.61,2429.88 ; v1@5822.61,2458.39 R741.1@5845,2428 5846,2428 R741.1@5846,2435 ; R741.1@5846,2435 5816.12,2456.43 R741.1@5849.1,2432.35
  Bottom w12: RC3.1@5885.44,2419.06 R741.1@5845,2428 ; RC3.1@5885.83,2434.98 R741.1@5845,2428 ; R741.1@5845,2428 5885.41,2428 RC3.1@5886.41,2427 R741.1@5845,2428
PLL_VC_CAP_1-CPU-RT0: C94.1 U1.B4 | length 266
  Top w8: U1.B4@2609.19,2397.14 2609.19,2413.91 U1.B4@2609.19,2397.14 ; U1.B4@2609.19,2397.14 v2(2609.1,2414) U1.B4@2609.19,2397.14
  Top w10: v2(2609.1,2414) v2@2609.19,2413.91
  Bottom w10: C94.1@2644.52,2441.44 v2(2609.1,2414) ; v2(2609.1,2414) 2621,2414 ; v2(2609.1,2414) C94.1@2645,2438.5 ; v2(2609.1,2414) 2621,2414 ; v2(2609.1,2414) 2621,2414 ; 2621,2414 C94.1@2645,2438.5 ; 2621,2414 C94.1@2645,2442 C94.1@2645,2438.5
PM_TXCLK-2_1-CPU-RT0: R682.1 TP601.1 U609.55 | length 231.4
  Top w10: 5485.97,2280 U609.55@5520.93,2281.58 ; 5510.99,2280 TP601.1@5468.73,2286.66 ; U609.55@5531.76,2281.58 5530.18,2280 5472.99,2280 5472.99,2282.4 TP601.1@5468.73,2286.66 ; TP601.1@5468.73,2286.66 5460.39,2295 R682.1@5428,2295 TP601.1@5468.73,2286.66
PM_TXCLK_1-CPU-RT0: R676.1 TP600.1 U607.55 | length 303.8
  Top w10: U607.55@4257.76,1863.58 4239.94,1863.58 ; R676.1@4153,1875 4152,1875 R676.1@4158.34,1868.66 ; R676.1@4153,1875 TP600.1@4194.73,1868.66 ; R676.1@4153,1875 TP600.1@4194.73,1868.66 ; R676.1@4158.34,1868.66 TP600.1@4194.73,1868.66 ; R676.1@4158.34,1868.66 TP600.1@4194.73,1868.66 ; TP600.1@4194.73,1868.66 4198.99,1864.4 4198.99,1863.58 4202.86,1859.71 4236.07,1859.71 ; TP600.1@4194.73,1868.66 4236.07,1859.71 ; 4236.07,1859.71 4239.94,1863.58 ; 4236.07,1859.71 U607.55@4246.93,1863.58 ; 4239.94,1863.58 U607.55@4246.93,1863.58 ; 4239.94,1863.58 U607.55@4246.93,1863.58
PMCT1_GE_2_4-ETHERNET: R806.2 T601.24 | length 114.7
  Top w15: T601.24@6398.05,676.23 R806.2@6398.05,636.01 T601.24@6398.05,710.48
PMCT1_GE_4-ETHERNET: R798.2 T600.24 | length 114.7
  Top w15: T600.24@5623.05,671.23 R798.2@5623.05,631.01 T600.24@5623.05,705.48
PMCT2_GE_2_4-ETHERNET: R805.2 T601.21 | length 114.7
  Top w15: T601.21@6248.05,676.23 R805.2@6248.05,636.01 T601.21@6248.05,710.48
PMCT2_GE_4-ETHERNET: R797.2 T600.21 | length 114.7
  Top w15: T600.21@5473.05,671.23 R797.2@5473.05,631.01 T600.21@5473.05,705.48
PMCT3_GE_2_4-ETHERNET: R804.2 T601.18 | length 114.7
  Top w15: T601.18@6098.05,676.23 R804.2@6098.05,636.01 T601.18@6098.05,710.48
PMCT3_GE_4-ETHERNET: R796.2 T600.18 | length 114.7
  Top w15: T600.18@5323.05,671.23 R796.2@5323.05,631.01 T600.18@5323.05,705.48
PMCT4_GE_2_4-ETHERNET: R803.2 T601.15 | length 114.7
  Top w15: T601.15@5948.05,676.23 R803.2@5948.05,636.01 T601.15@5948.05,710.48
PMCT4_GE_4-ETHERNET: R795.2 T600.15 | length 114.7
  Top w15: T600.15@5173.05,671.23 R795.2@5173.05,631.01 T600.15@5173.05,705.48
